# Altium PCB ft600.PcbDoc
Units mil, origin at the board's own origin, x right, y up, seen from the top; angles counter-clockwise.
Board outline 2000 x 1700 mil, 2 copper layers (Top Layer, Bottom Layer); 36 components, 41 nets, 168 pads, 31 vias.
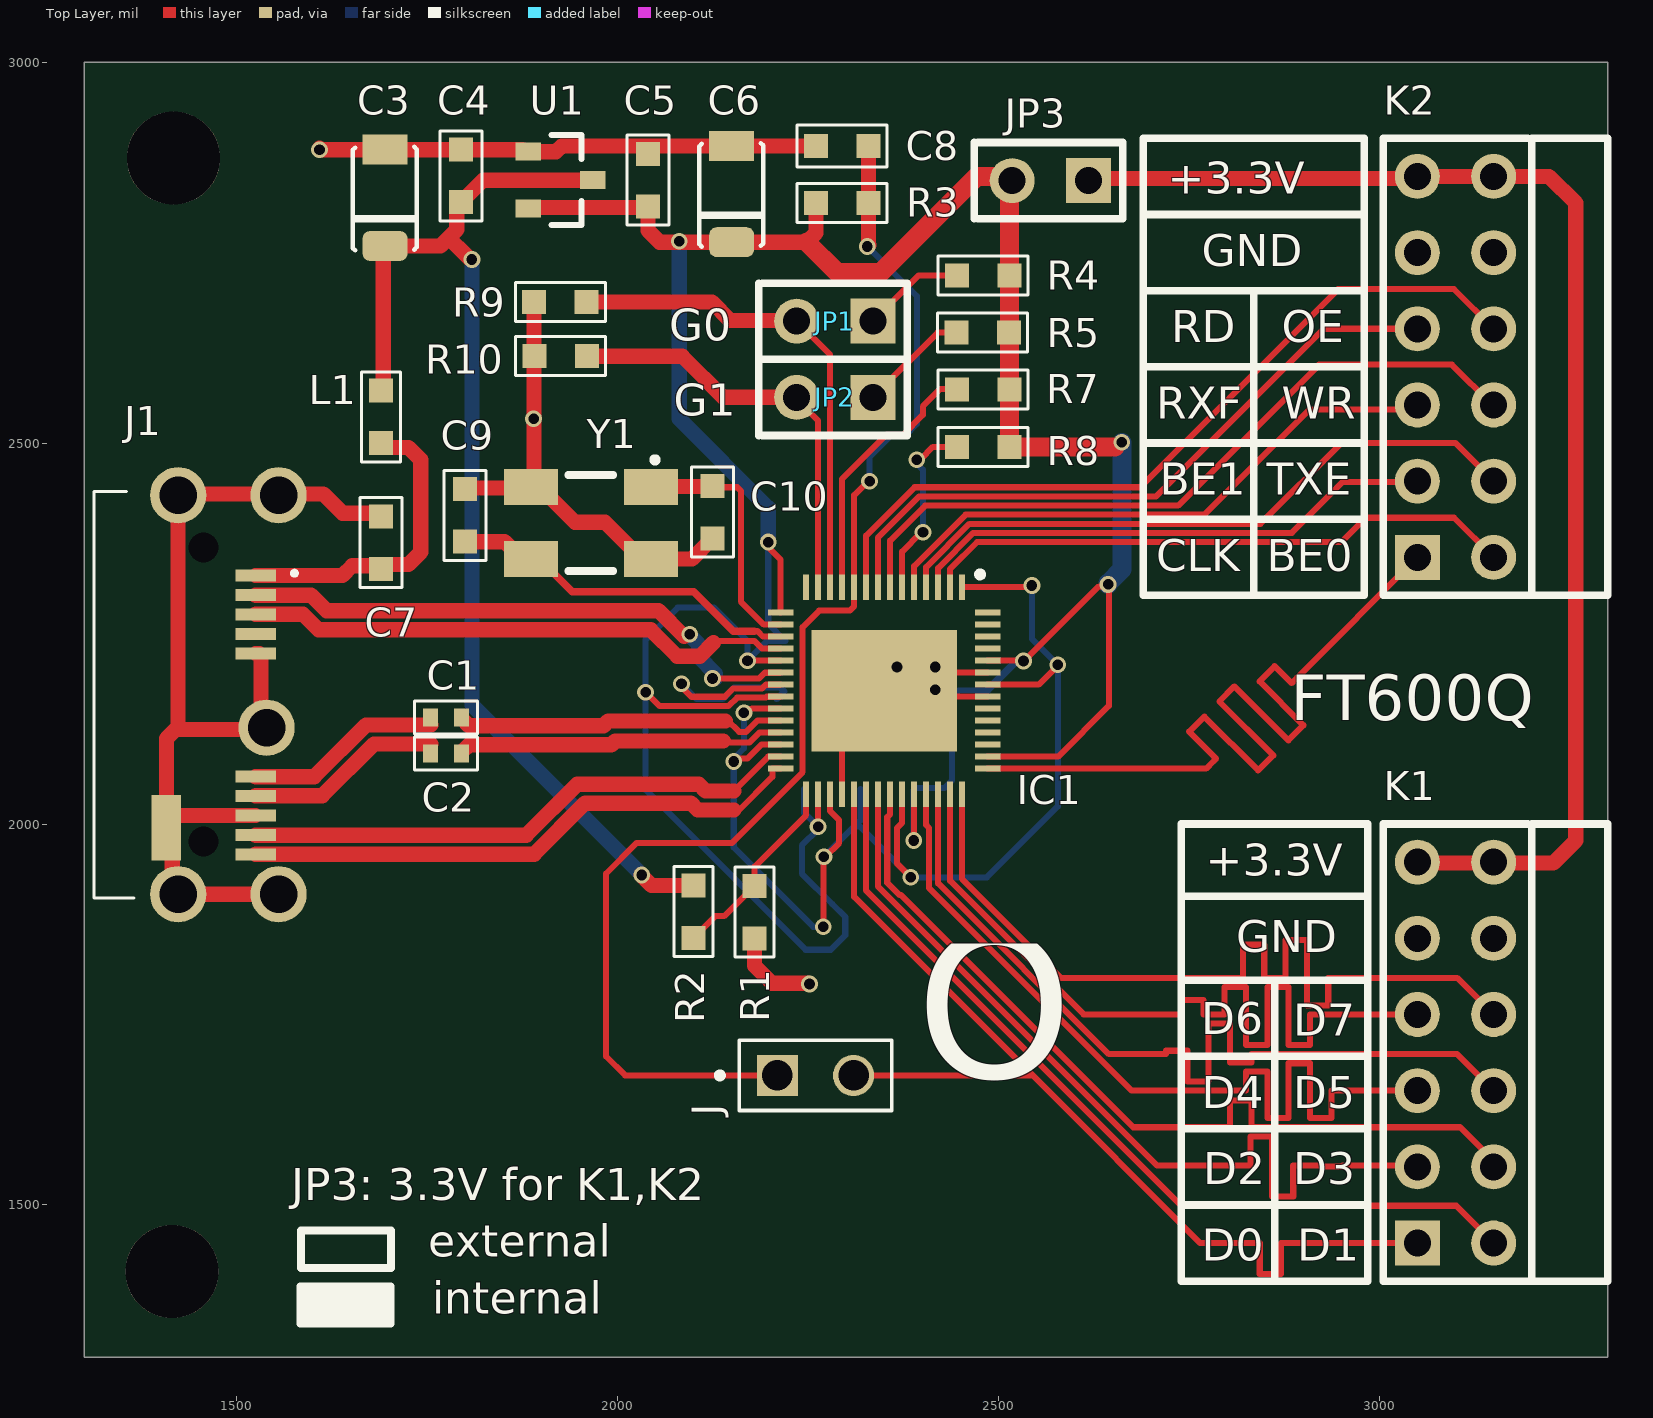
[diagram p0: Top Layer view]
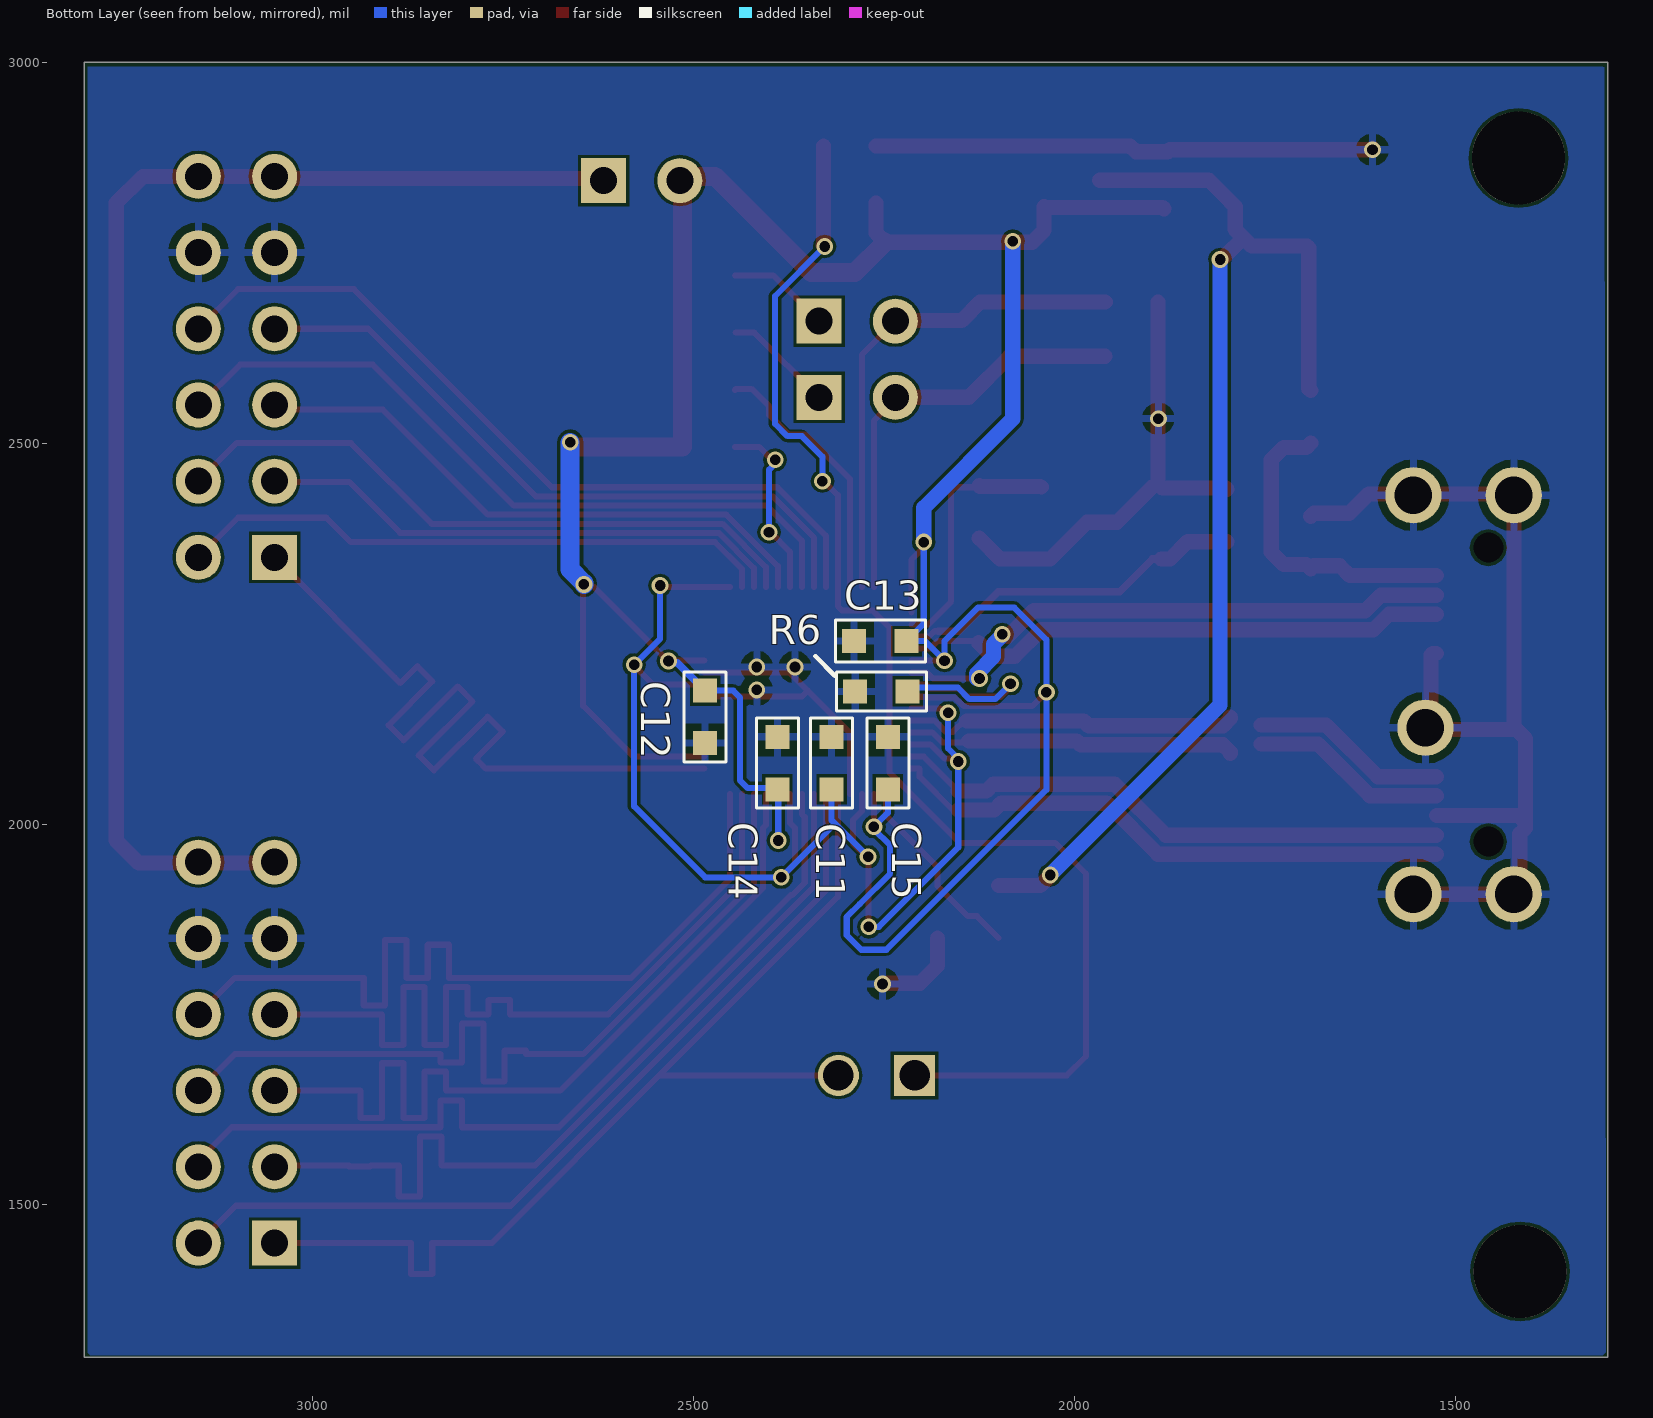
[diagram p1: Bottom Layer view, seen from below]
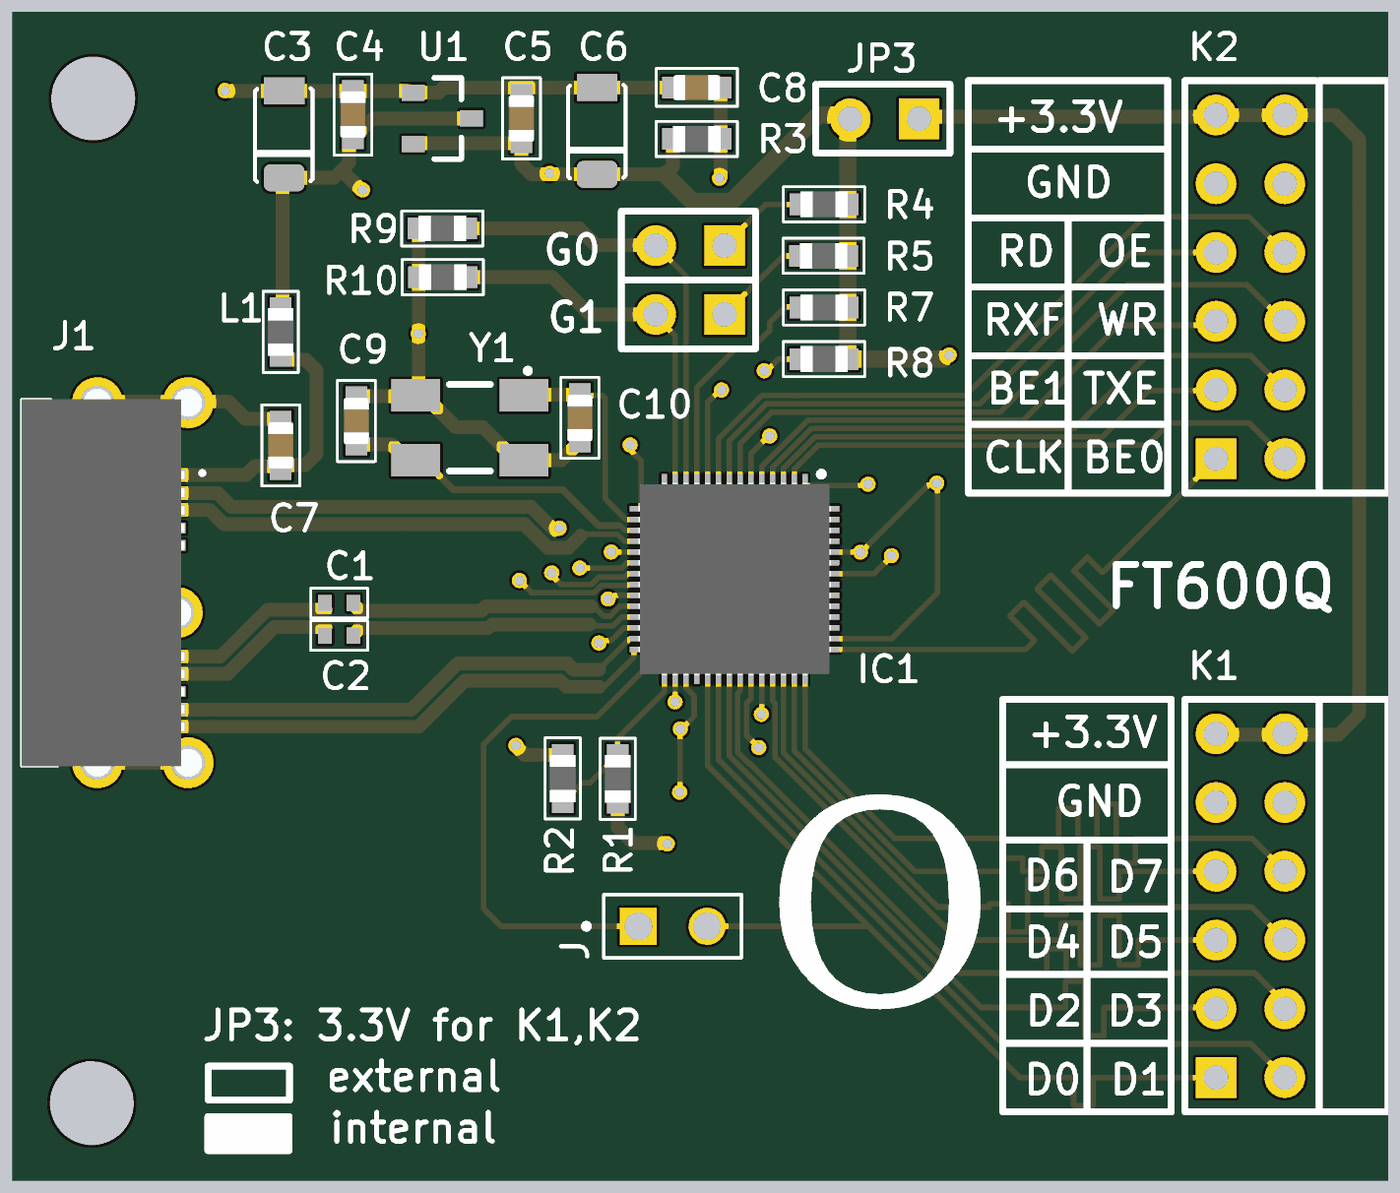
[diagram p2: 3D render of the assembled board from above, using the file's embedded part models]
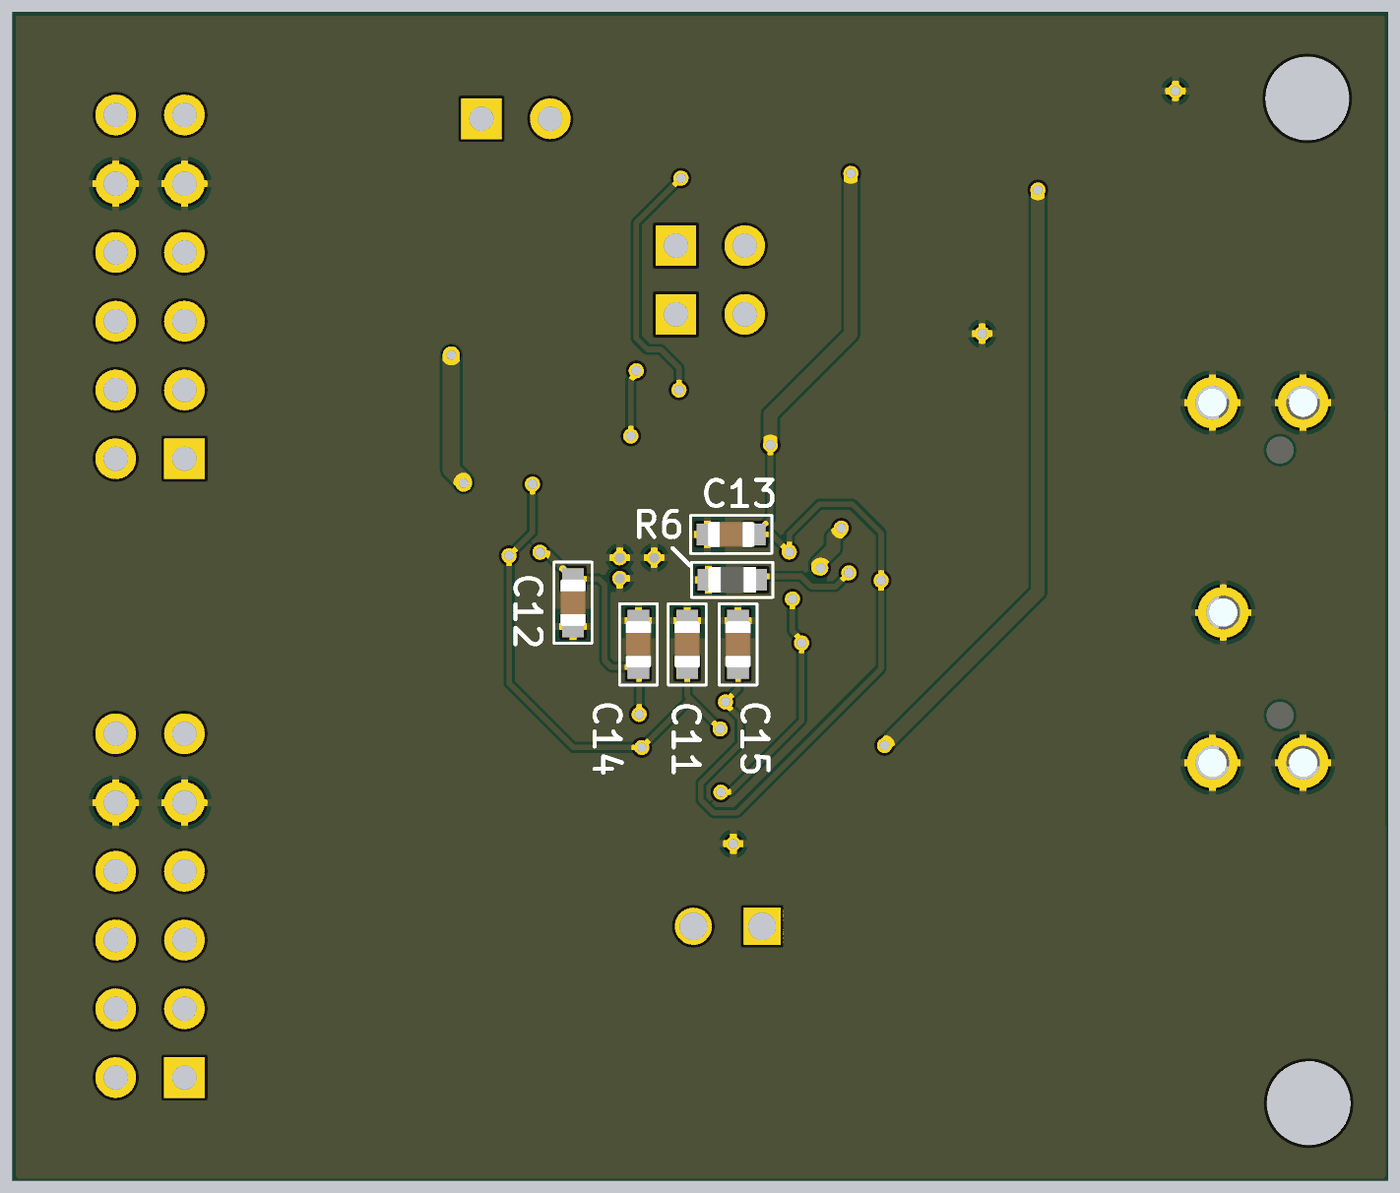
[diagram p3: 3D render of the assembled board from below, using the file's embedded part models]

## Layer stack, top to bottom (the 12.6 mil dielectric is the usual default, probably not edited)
Top Solder: solder mask 0.4, Solder Resist, Dk 3.5
Top Layer: signal copper 1.4
Dielectric 1: dielectric 12.6, FR-4, Dk 4.8
Bottom Layer: signal copper 1.4
Bottom Solder: solder mask 0.4, Solder Resist, Dk 3.5

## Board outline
1300,1300 3300,1300 3300,3000 1300,3000

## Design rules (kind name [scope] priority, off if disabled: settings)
Clearance [All] p1: gap=4 ignorepadtopadclearanceinfootprint=FALSE
DiffPairsRouting [All] p1: maxlimit=10 minlimit=5 mostfreqgap=5 toplayer_minwidth=8 toplayer_maxwidth=20 toplayer_prefwidth=20 bottomlayer_minwidth=8 bottomlayer_maxwidth=20 bottomlayer_prefwidth=20 maxuncoupledlength=200
HoleSize [All] p1: absolutevalues=TRUE maxlimit=200 minlimit=1 maxpercent=80.000 minpercent=20.000
MatchedLengths [InNetClass('data')] p1: tolerance=10 checknetsindiffpair=FALSE checkdiffpairvsdiffpair=TRUE checkxsignals=TRUE checkothers=TRUE
MinimumSolderMaskSliver [All] p1: minsoldermaskwidth=0
PolygonConnect [All] p1: connectstyle=Relief reliefconductorwidth=10 reliefentries=4 polygonreliefangle="90 Angle" airgapwidth=10
RoutingVias [All] p1: holewidth=16 width=26 viastyle="Through Hole" minholewidth=14 minwidth=22 maxholewidth=16 maxwidth=26
SilkToSilkClearance [All] p1: silktosilkclearance=7
SilkToSolderMaskClearance [IsPad] p1: minsilkscreentomaskgap=4 clearancetoexposedcopper=TRUE
SolderMaskExpansion [All] p1: expansion=4
Width [All] p1: maxlimit=50 minlimit=6 preferedwidth=10
25 further rules are at their usual default settings.

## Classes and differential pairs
net class data: CLK D0 D1 D2 D3 D4 D5 D6 D7
differential pair tx: +tx_P -tx_N
differential pair t: +t_P -t_N
differential pair rx: +rx_P -rx_N
differential pair d: +d_P -d_N

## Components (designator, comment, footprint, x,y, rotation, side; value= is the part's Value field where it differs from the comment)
C1 "cap0402" SM0402_3D_cap 1775,2140 r0 top value=0.1
C2 "cap0402" SM0402_3D_cap 1775,2092.75 r0 top value=0.1
C3 "CAP_POL_SMA" "CAP_POL_SMA (3216)" 1695,2758.78 r90 top
C4 "cap0603" "SM0603 _3D_cap" 1795,2850.55 r270 top value=0.1
C5 "cap0603" "SM0603 _3D_cap" 2040,2845 r270 top value=0.1
C6 "CAP_POL_SMA" "CAP_POL_SMA (3216)" 2150,2763.78 r90 top
C7 "cap0603" "SM0603 _3D_cap" 1690,2369.45 r270 top value=0.1uf
C8 "cap0603" "SM0603 _3D_cap" 2295,2890 r0 top value=0.1uf
C9 "cap0603" "SM0603 _3D_cap" 1800,2405 r270 top value=18pf
C10 "cap0603" "SM0603 _3D_cap" 2125,2409.45 r270 top value=18pf
C11 "cap0603" "SM0603 _3D_cap" 2318.97,2080 r270 bottom value=4.7uf
C12 "cap0603" "SM0603 _3D_cap" 2485,2140.55 r90 bottom value=0.1
C13 "cap0603" "SM0603 _3D_cap" 2255,2240 r180 bottom value=0.1
C14 "cap0603" "SM0603 _3D_cap" 2390,2080 r270 bottom value=0.1
C15 "cap0603" "SM0603 _3D_cap" 2245,2080 r270 bottom value=0.1
IC1 "FT600Q-T" QFN40P700X700X90-57N-D 2350,2175 r270 top
J "4-103321-4" TE_4-103321-4 2210,1670 r0 top
J1 "GSB343T33HR" GSB343T33HR 1429.33,2169.68 r270 top
JP1 "JUMPER2" JUMPER2 2335.32,2659.97 r270 top
JP2 "JUMPER2" JUMPER2 2335.32,2559.97 r270 top
JP3 "JUMPER2" JUMPER2 2618.11,2844.49 r270 top
K1 "PMOD_6x2_ra_male" PMOD_6x2_right_ANGLE 3050,1450 r90 top
K2 "PMOD_6x2_ra_male" PMOD_6x2_right_ANGLE 3050,2350 r90 top
L1 "75R@100MHz" SM0603_3D_res 1690,2534.45 r90 top
R1 "10k" SM0603_3D_res 2180,1884.45 r270 top value=4k7
R2 "4k7" SM0603_3D_res 2100,1885 r90 top
R3 "10k" SM0603_3D_res 2295,2815 r180 top value=4k7
R4 "2k" SM0603_3D_res 2480,2720 r180 top value=4k7
R5 "2k" SM0603_3D_res 2479.45,2645 r180 top value=4k7
R6 "1.6k 1%" SM0603_3D_res 2253.45,2173.97 r180 bottom value=4k7
R7 "4k7" SM0603_3D_res 2480,2570 r180 top
R8 "4k7" SM0603_3D_res 2480,2495 r180 top
R9 "36k" SM0603_3D_res 1925,2685 r180 top value=4k7
R10 "36k" SM0603_3D_res 1925.55,2613.97 r180 top value=4k7
U1 "XC6206" SOT-23 1925,2845 r0 top
Y1 "ABM3B-30MHZ" ABM3B 1965,2395 r180 top

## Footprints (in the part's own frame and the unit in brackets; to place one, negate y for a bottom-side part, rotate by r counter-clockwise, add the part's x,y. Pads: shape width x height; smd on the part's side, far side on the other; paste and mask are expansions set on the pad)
ABM3B [mm]
  rect 1.8x1.2 smd: 1(-2,-1.2) 2(2,-1.2) 3(2,1.2) 4(-2,1.2)
  silkscreen extent -2.2,-2.16 0.75,1.6
"CAP_POL_SMA (3216)" [mm] "tantalum capacitor SMA"
  rrect50% 1x1.5 smd: 1(-0.004,0)
  rect 1x1.5 smd: 2(3.206,0)
  silkscreen extent -0.15,-1.05 3.3,1.08
GSB343T33HR [mm]
  rect 0.4x1.35 smd: 1(-3.975,2.43) 2(-3.325,2.43) 3(-2.675,2.43) 4(-2.025,2.43) 5(-1.375,2.43) 6(2.725,2.43) 7(3.375,2.43) 8(4.025,2.43) 9(4.675,2.43) 10(5.325,2.43)
  round 1.875 hole 1.25: MH1(-6.65,-0.15) MH2(6.65,-0.15) MH3(6.65,3.2) MH4(1.1,2.8) MH5(-6.65,3.2)
  round 0.5 hole 1 unplated: MH6(-4.9,0.7) MH7(4.9,0.7)
  rect 2.18x0.98 smd: MP1(4.44,-0.54)
  silkscreen extent -6.78,-2.95 6.78,3.77, body extent -7.17,-2.95 7.17,3.72, height 5.35
JUMPER2 [mm]
  rect 1.5x1.5 hole 0.9: 1(0,0)
  round 1.5 hole 0.9: 2(0,-2.54)
  silkscreen extent -1.27,-3.81 1.27,1.14
PMOD_6x2_right_ANGLE [mm] "2.54 mm right angle 6x2 pins"
  rect 1.5x1.5 hole 0.9: 1(0,0)
  round 1.5 hole 0.9: 2(2.54,0) 3(5.08,0) 4(7.62,0) 5(10.16,0) 6(12.7,0) 7(0,-2.54) 8(2.54,-2.54) 9(5.08,-2.54) 10(7.62,-2.54) 11(10.16,-2.54) 12(12.7,-2.54)
  silkscreen extent -1.27,-6.35 13.97,1.14
QFN40P700X700X90-57N-D [mm]
  rect 0.85x0.2 smd: 1(-3.45,2.6) 2(-3.45,2.2) 3(-3.45,1.8) 4(-3.45,1.4) 5(-3.45,1) 6(-3.45,0.6) 7(-3.45,0.2) 8(-3.45,-0.2) 9(-3.45,-0.6) 10(-3.45,-1) 11(-3.45,-1.4) 12(-3.45,-1.8) 13(-3.45,-2.2) 14(-3.45,-2.6) 29(3.45,-2.6) 30(3.45,-2.2) 31(3.45,-1.8) 32(3.45,-1.4) 33(3.45,-1) 34(3.45,-0.6) 35(3.45,-0.2) 36(3.45,0.2) 37(3.45,0.6) 38(3.45,1) 39(3.45,1.4) 40(3.45,1.8) 41(3.45,2.2) 42(3.45,2.6)
  rect 0.2x0.85 smd: 15(-2.6,-3.45) 16(-2.2,-3.45) 17(-1.8,-3.45) 18(-1.4,-3.45) 19(-1,-3.45) 20(-0.6,-3.45) 21(-0.2,-3.45) 22(0.2,-3.45) 23(0.6,-3.45) 24(1,-3.45) 25(1.4,-3.45) 26(1.8,-3.45) 27(2.2,-3.45) 28(2.6,-3.45) 43(2.6,3.45) 44(2.2,3.45) 45(1.8,3.45) 46(1.4,3.45) 47(1,3.45) 48(0.6,3.45) 49(0.2,3.45) 50(-0.2,3.45) 51(-0.6,3.45) 52(-1,3.45) 53(-1.4,3.45) 54(-1.8,3.45) 55(-2.2,3.45) 56(-2.6,3.45)
  rect 4.05x4.85 smd: 57(0,0)
  silkscreen extent -3.97,3.1 -3.78,3.3, body extent -3.55,-3.55 3.55,3.55, height 0.9
SM0402_3D_cap [mm] "0402 cap"
  rect 0.5x0.6 smd: 1(-0.525,0) 2(0.525,0)
  silkscreen extent -1.05,-0.55 1.05,0.55, body extent -0.53,-0.25 0.53,0.25, height 0.4
"SM0603 _3D_cap" [mm] "standard  0603 inch size"
  rect 0.8x0.8 smd: 1(-0.875,0) 2(0.875,0)
  silkscreen extent -1.5,-0.7 1.5,0.7, body extent -0.87,-0.47 0.88,0.48, height 0.87
SM0603_3D_res [mm] "0603 inch resistor"
  rect 0.8x0.8 smd: 1(-0.875,0) 2(0.875,0)
  silkscreen extent -1.5,-0.65 1.5,0.65, body extent -0.87,-0.47 0.88,0.48, height 0.55
SOT-23 [mm] "SOT23_L from misc devices"
  rect 0.85x0.6 smd: 1(-1.075,0.95) 2(-1.075,-0.95) 3(1.075,0)
  silkscreen extent -0.3,-1.5 0.7,1.5, body extent -0.7,-1.5 0.7,1.5, height 1.1
TE_4-103321-4 [mm]
  rect 1.37x1.37 hole 1.02: 1(0,0)
  round 1.37 hole 1.02: 2(2.54,0)
  silkscreen extent -2.02,-1.17 3.81,1.17

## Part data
C1 C2: "Capacitor  0402 inch"
C3 C6: "CAP_POL_SMA(3216)"
C4 C5 C7 C8 C9 C10 C11 C12 C13 C14 C15: "Capacitor  0603 inch"
IC1: "Integrated Circuit", Manufacturer_Name="FTDI Chip", Mouser Part Number=895-FT600Q-T
J: "Conn Unshrouded Header HDR 2 POS 2.54mm Solder ST Thru-Hole Carton", Package=None
J1: "Connector", Manufacturer_Name=Amphenol, Mouser Part Number=523-GSB343T33HR
K1 K2: "PMOD_6x2_right_angle"
L1: "chip inductance 0603", Case=0805, Manufacturer=MURATA, Manufacturer Part Number=BLM21BB750SN1D, Part Number=IND0805_MURATA_BLM21BB750SN1D, Power=700mA, Resistance=0.16R, Tolerance=±25%
R1 R2 R3 R4 R5 R6 R7 R8 R9 R10: "Res_0603_EU", Case=1206, Manufacturer=GENERIC, Manufacturer1 ComponentHeight=0.65mm, Manufacturer1 Example="NIC COMPONENT", Manufacturer1 Part Number=NRC12F4701TRF, Manufacturer Part Number=R1206_4K7_1%_0.25W_100PPM, Power=0.25W, Tolerance=±1%
U1: "SOT-23-3 ldo"
Y1: library part ABM3B-11.0592MHZ-10-1-U-T, "Crystal or Oscillator", Manufacturer_Name=ABRACON, Mouser Part Number=815-ABM3B-11.0592-T

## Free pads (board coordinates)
  round 122.05 hole 122.05 unplated: 0(1415.3,1412.68) 0(1417.32,2874.02)

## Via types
v1: diameter 22, hole 14, Top Layer to Bottom Layer, 31 vias

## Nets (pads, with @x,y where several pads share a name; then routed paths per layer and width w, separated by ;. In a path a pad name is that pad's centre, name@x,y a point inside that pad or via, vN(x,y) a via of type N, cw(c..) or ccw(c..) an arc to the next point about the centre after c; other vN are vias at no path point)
+3.3V: C5.2 C6.1 C12.2 C13.2 C14.2 C15.2 IC1.15 IC1.19 IC1.22 IC1.30 IC1.38 IC1.44 IC1.52 JP3.2 R3.2 R4.1 R5.1 R7.1 R8.1 U1.2 | length 4426.3
  Top Layer w8: v1(2037,2173) 2055,2155 2146,2155 2157,2166 2194.94,2166 2196,2167.06 2214.11,2167.06 IC1.22 ; v1@2170,2215 v1(2170.63,2214.37) IC1.19 ; v1@2197,2364 2214.17,2346.83 IC1.15 ; v1(2263.39,1996.39) IC1.30 ; v1(2388.87,1978.29) 2388.87,1982.87 2389.37,1983.37 IC1.38 ; IC1.44 2578.39,2088.39 2645,2155 2645,2313.5 v1(2644,2314.5) 2641.32,2311.82 2631.82,2311.82 v1@2540.58,2220.58 ; IC1.52 v1@2533,2214.37
  Top Layer w20: U1.2 1884.15,2809.07 2038.53,2809.07 C5.2 2040,2779 2055.38,2763.62 2081,2763.62 C6.1 2248.62,2763.62 2260.55,2775.55 R3.2
  Top Layer w25: 2248.62,2763.62 2288.25,2724 2346,2724 2472,2850 2517,2850 2514.45,2847.45 R4.1 2514.45,2645 R7.1 R8.1 v1@2653,2495
  Bottom Layer w8: v1(2198,2370) 2198,2262.55 C13.2 2196.26,2240 v1(2170.63,2214.37) 2170.63,2240.37 2127,2284 2079,2284 2037,2242 v1(2037,2173) 2037,2045 2247,1835 2280,1835 2299,1854 2299,1878 2282,1895 2242,1935 2242,1972 2263.39,1993.39 v1(2263.39,1996.39) 2245,2014.77 C15.2 ; v1@2388.87,1975.13 v1(2388.87,1978.29) 2388.87,2044.43 C14.2 2391.45,2047 2429,2047 2439,2057 2439,2166 2448,2175 C12.2
  Bottom Layer w10: C12.2 2521.7,2211.7 2530.7,2211.7 v1(2533,2214)
  Bottom Layer w20: v1(2081,2765) 2081,2532 2198,2415 v1(2198,2370)
  Bottom Layer w25: v1(2644,2314.5) 2644,2316 2662,2334 v1(2662,2501)
be0: IC1.2 K2.7 | length 786.7
  Top Layer w8: IC1.2 2436.68,2310.89 2436.68,2334.77 2471.91,2370 2950,2370 2982,2402 3098,2402 K2.7
be1: IC1.3 K2.2 | length 701.5
  Top Layer w8: IC1.3 2420.87,2335.93 2466.94,2382 2885,2382 2952,2449 3049,2449 K2.2
C47: C11.2 IC1.1 IC1.23 IC1.26 IC1.31 IC1.37 IC1.50 | length 1704.4
  Top Layer w8: v1(2152.67,2082) 2156.5,2085.83 2170.64,2085.83 2188.95,2104.13 IC1.26 ; v1@2166,2145 2168,2145 2174,2151 2176,2151 2176.38,2151.38 IC1.23 ; v1(2270,1865) 2270.5,1865.5 2270.5,1956.5 v1(2271,1957) 2273,1957 2291,1975 2291,2005 2279.2,2016.8 2279.2,2039.11 IC1.31 ; IC1.37 2373.62,2001.62 2367,1995 2367,1948 v1(2385,1930) ; IC1.1 2539.83,2310.83 v1@2540,2311 ; IC1.50 2552.87,2182.87 v1@2575,2205
  Bottom Layer w8: v1(2166,2146) 2166,2099.11 2152.67,2085.79 v1(2152.67,2082) 2152.67,1969.33 2257,1865 v1(2270,1865) ; v1(2271,1957) 2311,1997 ; C11.2 2318.96,2004.96 2311,1997 ; v1(2544,2313) 2544,2243 v1(2578,2209) 2578,2023 2485,1930 v1(2385,1930) 2318,1997 2311,1997
CLK: IC1.43 K2.1 | length 1141.8
  Top Layer w8: IC1.43 2772.64,2072.64 2783,2083 2785.83,2085.83 2750.47,2121.18 2770.27,2140.98 2840.98,2070.27 2860.78,2090.07 2790.07,2160.78 2809.87,2180.58 2880.58,2109.87 2900.38,2129.67 2842.84,2187.21 2862.64,2207 2884.82,2184.82 2892,2192 K2.1
D0: IC1.33 J.2 K1.1 | length 1379.5
  Top Layer w8: J.2@2310.63,1670.63 J.2 2545,1670 ; IC1.33 2310.63,1904.37 2545,1670 ; K1.1 2885,1450 2871,1450 2871,1409.39 2843,1409.39 2843,1450 2804,1450 2765,1450 2545,1670
D0_rst: C8.2 IC1.10 J.1 R3.1 | length 1729.8
  Top Layer w8: J.1 2010,1670 1985,1695 1985,1935 2025,1975 2150,1975 2243.11,2068.11 2243.11,2258.35 2264.76,2280 2305,2280 2310.57,2285.57 IC1.10 IC1.10 2310.63,2431.63 2327,2448 v1@2327,2449
  Top Layer w20: C8.2@2329.45,2890 R3.1 2329.45,2760.55 v1@2330,2760
  Bottom Layer w8: v1(2328,2758) 2393,2693 2393,2525 2377,2509 2358,2509 2331,2482 v1(2331,2450)
D1: IC1.34 K1.7 | length 1141.8
  Top Layer w8: IC1.34 2326.38,1912.62 2339.34,1899.66 2740,1499 3101,1499 K1.7
D2: IC1.35 K1.2 | length 1142.6
  Top Layer w8: IC1.35 2342.13,1917.87 2353,1907 2469,1791 2708,1552 2814,1552 2831,1552 2831,1590 2859,1590 2859,1511 2887,1511 2887,1552 2891,1552 2892,1552 2924,1552 2924,1550.5 2952,1550.5 2952,1552 2989,1552 3048,1552 K1.2
D3: IC1.36 K1.8 | length 1143.6
  Top Layer w8: IC1.36 2357.87,2012.75 2354.13,2009 2354.13,1922.84 2369.97,1907 2372,1907 2677,1602 2800,1602 2804,1602 2804,1637.36 2832,1637.36 2832,1602 2912,1602 3106,1602 3150,1558 K1.8
D4: IC1.39 K1.3 | length 1141.8
  Top Layer w8: IC1.39 2405.12,1998.75 2408.87,1995 2408.87,1916.13 2675,1650 2759,1650 2825,1650 2825,1674.92 2853,1674.92 2853,1614 2881,1614 2881,1686 2909,1686 2909,1614 2937,1614 2937,1650 2941,1650 K1.3
D5: IC1.40 K1.9 | length 1141.8
  Top Layer w8: IC1.40 2420.87,1922.13 2645,1698 2704,1698 2720,1698 2720,1702.37 2748,1702.37 2748,1662 2776,1662 2776,1738 2804,1738 2804,1686.92 2832,1686.92 2832,1698 2836,1698 3102,1698 K1.9
D6: IC1.41 K1.4 | length 1141.8
  Top Layer w8: IC1.41 2436.61,1925.39 2612,1750 2722,1750 2741,1750 2741,1768.99 2769,1768.99 2769,1750 2797,1750 2797,1786 2825,1786 2825,1710 2853,1710 2853,1786 2881,1786 2881,1710 2909,1710 2909,1750 2913,1750 K1.4
D7: IC1.42 K1.10 | length 1141.8
  Top Layer w8: IC1.42 2452.36,1927.64 2582,1798 2683,1798 2821,1798 2821,1841.52 2849,1841.52 2849,1798 2877,1798 2877,1848 2905,1848 2905,1762 2933,1762 2933,1798 2937,1798 3102,1798 K1.10
d_N: IC1.20 J1.2 | length 753.6
  Top Layer w8: v1(2124.85,2191) 2186,2191 2193.56,2198.56 2214.11,2198.56 IC1.20
  Top Layer w20: J1.2 1525.3,2300.3 1597.71,2300.3 1618,2280 2054,2280 v1@2087.67,2246.33
  Bottom Layer w20: v1(2095,2249) 2095,2247.38 2106.33,2236.05 2106.33,2219.67 2128.85,2197.15 2128.85,2191.15 2128.7,2191 v1(2124.85,2191)
d_P: IC1.18 J1.3 | length 724.4
  Top Layer w8: 2126,2238 2128,2240 2180,2240 2189.88,2230.12 IC1.18
  Top Layer w20: J1.3 1525.3,2275.3 1587.35,2275.3 1607.65,2255 2043.64,2255 2078.47,2220.18 2108.18,2220.18 2126,2238
g0: IC1.12 JP1.2 R9.1 | length 653.5
  Top Layer w8: JP1.2 2279.13,2616.16 IC1.12
  Top Layer w20: R9.1 2124,2685 2148,2661 2234.29,2661 JP1.2
g1: IC1.13 JP2.2 R10.1 | length 558.5
  Top Layer w8: JP2.2 2235.32,2557.37 2263.39,2529.3 IC1.13
  Top Layer w20: R10.1 2085.04,2613.96 2139.03,2559.97 JP2.2
GND: C3.2 C4.1 C5.1 C6.2 C7.1 C8.1 C9.1 C10.2 C11.1 C12.1 C13.1 C14.1 C15.1 IC1.32 IC1.49 IC1.51 IC1.57 J1.5 J1.8 J1.MH1 J1.MH2 J1.MH3 J1.MH4 J1.MH5 J1.MP1 K1.5 K1.11 K2.5 K2.11 R1.2 R6.1 R9.2 R10.2 U1.1 Y1.2 Y1.4 | length 3112
  Top Layer w8: IC1.32 2294.88,2119.88 IC1.57 ; IC1.49 2357.87,2167.13 IC1.57 ; IC1.51 2373.62,2198.62 IC1.57
  Top Layer w20: J1.8 1417.36,2011.22 J1.MP1@1408.07,2001.93 ; J1.5 1530.16,2223.82 1532.28,2221.69 1532.28,2133.66 J1.MH4 ; J1.MH4@1532.28,2124 1419.79,2124 ; J1.MH3 J1.MH2 1415.75,1915.55 1415.75,1987.2 J1.MP1 J1.MP1@1408.07,2001.93 ; v1@1609,2887 1611,2885 C3.2 C4.1 1875.16,2885 1877.76,2882.4 U1.1 1919.4,2882.4 1927,2890 C6.2 C8.1 ; C7.1 1685.9,2408 1639,2408 1614,2433 1424.93,2433 J1.MH1 1423.2,2431.28 1423.2,2127.42 1419.79,2124 ; C9.1 1801.4,2440.85 1884.86,2440.85 Y1.2 1890.55,2446.53 R9.2 ; Y1.2@1898.07,2442.24 1944.31,2396 1983.69,2396 2031.93,2347.76 Y1.4 2097.76,2347.76 C10.2 ; R1.2 2180,1814 2203,1791 v1@2250,1791 ; J1.MP1@1408.07,2001.93 1408.07,2112.28 1419.79,2124
  other v1: 2252,1790 2417,2176 2367,2206 2417,2206 1890,2532 1609,2885
NetC3_1: C3.1 C4.2 L1.2 R2.2 U1.3 | length 1530
  Top Layer w20: L1.2 1692.5,2571.4 1692.5,2756.12 C3.1 1767.62,2758.62 1778.44,2769.44 ; v1@1805,2743 1802,2746 1801.88,2746 1778.44,2769.44 ; U1.3 1823.9,2845 C4.2 1789.25,2810.35 1789.25,2780.25 1778.44,2769.44 ; v1@2031,1933 2044.55,1919.45 R2.2
  Bottom Layer w20: v1(1809,2741) 1809,2156 v1(2032,1933)
NetJP1_1: JP1.1 R4.2 | length 135.1
  Top Layer w8: JP1.1 2395.35,2720 R4.2
NetJP2_1: JP2.1 R5.2 | length 144.9
  Top Layer w8: JP2.1 2420.35,2645 R5.2
oe: IC1.9 K2.10 | length 1046.8
  Top Layer w8: IC1.9 2326.38,2378.38 2390,2442 2686,2442 2946,2702 3098,2702 K2.10
rd: IC1.8 K2.4 | length 886.6
  Top Layer w8: IC1.8 2342.13,2376.13 2396,2430 2707,2430 2927,2650 K2.4
ref: IC1.21 R6.2 | length 311.8
  Top Layer w8: v1(2084,2184) 2084,2180 2097,2167 2141,2167 2152,2178 2189.97,2178 2194.78,2182.81 2214.11,2182.81 IC1.21
  Bottom Layer w8: v1(2084,2184) 2104,2164 2138,2164 2153,2179 2213.97,2179 R6.2 R6.2@2209.03,2164
rx_N: IC1.27 J1.9 | length 736.7
  Top Layer w8: 2154.78,2045.22 2197.94,2088.39 IC1.27
  Top Layer w20: J1.9 1525.3,1985.33 1880.33,1985.33 1947.32,2052.32 2106.71,2052.32 2115.75,2043.28 2152.84,2043.28
rx_P: IC1.28 J1.10 | length 744.8
  Top Layer w8: 2158.27,2016.73 2203.31,2061.77 2203.31,2072.57 2203.37,2072.64 IC1.28
  Top Layer w20: J1.10 1525.3,1960.33 1890.69,1960.33 1957.68,2027.32 2096.35,2027.32 2105.39,2018.28 2152.84,2018.28
rxf: IC1.5 K2.3 | length 775.8
  Top Layer w8: IC1.5 2389.37,2338.37 2457,2406 2770,2406 2908,2544 3044,2544 K2.3
siwu: IC1.6 R8.2 | length 236.8
  Top Layer w8: IC1.6 2373.62,2357.62 2398,2382 v1@2399,2382 ; v1@2398,2477 2398,2479 2414,2495 R8.2
  Bottom Layer w8: v1(2393,2478) 2393,2473.13 2401,2465.13 v1(2401,2383)
t_N: C1.1 J1.6 | length 258.2
  Top Layer w20: J1.6 1525.3,2062.11 1602.11,2062.11 1670,2130 C1.1@1755,2130
t_P: C2.1 J1.7 | length 258.2
  Top Layer w20: J1.7 1525.3,2037.11 1612.46,2037.11 1680.36,2105 1755,2105
tx_N: C1.2 IC1.24 | length 437.4
  Top Layer w8: 2143.72,2137 2159.72,2121 2169,2121 2183.63,2135.63 IC1.24
  Top Layer w20: C1.2 1795.67,2138.35 1805.14,2128.88 1981.6,2128.88 1987.82,2135.1 2141.82,2135.1
tx_P: C2.2 IC1.25 | length 432.4
  Top Layer w8: 2139,2109 2141,2107 2173.38,2107 2186.27,2119.88 IC1.25
  Top Layer w20: C2.2 1795.67,2094.4 1805.14,2103.88 1991.95,2103.88 1997.08,2109 2139,2109
txe: IC1.4 K2.8 | length 859.4
  Top Layer w8: IC1.4 2405.12,2337.15 2461.97,2394 2844,2394 2950,2500 3100,2500 K2.8
VB: C7.2 J1.1 L1.1 | length 415.2
  Top Layer w20: J1.1 1639.18,2326.18 1652,2339 1686,2339 C7.2 1695.75,2340.75 1725.75,2340.75 1742,2357 1742,2478 1725.75,2494.25 1695.75,2494.25 L1.1
Vbus: IC1.29 R1.1 R2.1 | length 256.6
  Top Layer w8: R2.1 2128.44,1879 2140.1,1879 R1.1 2180,1944 2247.64,2011.64 IC1.29
Vcc: JP3.1 K1.6 K1.12 K2.6 K2.12 | length 1713.8
  Top Layer w20: JP3.1 2620.87,2847.24 3047.24,2847.24 K2.6 K2.12 3222.83,2850 3257.87,2814.96 3257.87,1978.35 3228.35,1948.82 3051.18,1948.82 K1.6
wake: IC1.11 R7.2 | length 348.5
  Top Layer w8: IC1.11 2294.88,2452.88 2353,2511 2375,2511 2401,2537 2401,2548 2424,2571 2444.55,2571 R7.2
wr: IC1.7 K2.9 | length 970.9
  Top Layer w8: IC1.7 2357.87,2371.87 2404,2418 2736,2418 2921,2603 3095,2603 3148,2550 K2.9
xi: C10.1 IC1.16 Y1.1 | length 331.7
  Top Layer w8: C10.1 2126.9,2442 2157.31,2442 2162,2437.31 2162,2292 2192.32,2261.68 2214.11,2261.68 IC1.16
  Top Layer w20: Y1.1 2044.57,2443.07 2124.17,2443.07 C10.1
xo: C9.2 IC1.17 Y1.3 | length 465.8
  Top Layer w8: 2179.62,2253 2184,2253 2191.07,2245.93 2214.11,2245.93 IC1.17
  Top Layer w10: Y1.3 1898.07,2347.76 1940.83,2305 2100,2305 2152,2253 2179.62,2253
  Top Layer w20: C9.2 1851.66,2370.55 1874.45,2347.76 Y1.3
pads on no net: IC1.14 IC1.45 IC1.46 IC1.47 IC1.48 IC1.53 IC1.54 IC1.55 IC1.56 J1.4 J1.MH6 J1.MH7

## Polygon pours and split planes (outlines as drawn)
GND on Bottom Layer "GND_L02_P000" (solid, pour order 0): 1305,2996 1307,2994 3295,2994 3295,1306 3292,1303 1303,1303

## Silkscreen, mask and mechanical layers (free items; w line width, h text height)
Top Overlay:
  lines w10: 1584.65,1387.8 1696.95,1387.8 1691.14,1381.99 1588.68,1381.99 1584.09,1377.4 1693.25,1377.4 1702.2,1368.44 1584.09,1368.44 1594.27,1358.27 1596,1360 1695,1360 1700,1355 1590,1355 1584.09,1349.09 1694.09,1349.09 ; 2690,2500 2980,2500 ; 2690,2800 2980,2800 ; 2695,2400 2980,2400 ; 2695,2600 2980,2600 ; 2695,2700 2975,2700 ; 2740,1500 2985,1500 ; 2740,1600 2985,1600 ; 2740,1695 2985,1695 ; 2740,1795 2985,1795 ; 2740,1905 2985,1905 ; 2835,2300 2835,2695 ; 2862.5,1400 2862.5,1795 ; 1584.09,1343.84 1584.09,1393.05 1702.2,1393.05 1702.2,1343.84 1584.09,1343.84 ; 1584.65,1417.32 1702.76,1417.32 1702.76,1466.54 1584.65,1466.54 1584.65,1417.32 ; 2690,2300 2690,2310 2690,2900 2980,2900 2980,2300 2690,2300 ; 2740,1400 2985,1400 2985,2000 2740,2000 2740,1400
  text "+3.3V" at 2722,2827 h42
  text "GND" at 2767,2732 h42
  text "G0" at 2068,2634 h42
  text "RD" at 2727,2632 h42
  text "OE" at 2872,2632 h42
  text "G1" at 2074,2536 h42
  text "RXF" at 2707,2532 h42
  text "WR" at 2872,2532 h42
  text "BE1" at 2712,2432 h42
  text "TXE" at 2852,2432 h42
  text "CLK" at 2707,2332 h42
  text "BE0" at 2852,2332 h42
  text "FT600Q" at 2884.02,2135.98 h60
  text "+3.3V" at 2772,1932 h42
  text "GND" at 2812,1832 h42
  text "D6" at 2766,1724 h42
  text "D7" at 2887,1722 h42
  text "D4" at 2767,1627 h42
  text "D5" at 2887,1627 h42
  text "O" at 2391.73,1555.12 h590.55
  text "D2" at 2769,1527 h42
  text "D3" at 2887,1527 h42
  text "JP3: 3.3V for K1,K2" at 1572,1506 h42
  text "external" at 1752,1432 h42
  text "D0" at 2767,1427 h42
  text "D1" at 2892,1427 h42
  text "internal" at 1757,1357 h42
Bottom Overlay:
  lines w6: 2314.56,2194.56 2340,2220
Mechanical 1:
  the board outline again, w10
